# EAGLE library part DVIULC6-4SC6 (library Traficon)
Ultra low capacitance ESD protection
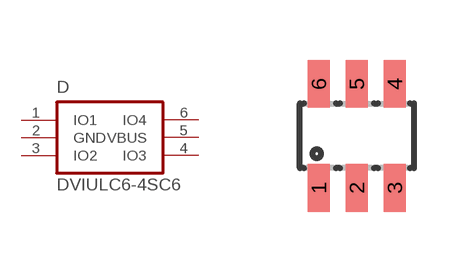
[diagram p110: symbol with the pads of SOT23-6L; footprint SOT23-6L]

Designator prefix D

## DVIULC6-4SC6  [SOT23-6L]
1  IO1
2  GND
3  IO2
4  IO3
5  VBUS
6  IO4

## Footprint SOT23-6L (pad centres in mm)
Small Outline Transistor
smd 0.55 x 1.2: 1 -0.95,-1.3; 2 0,-1.3; 3 0.95,-1.3; 4 0.95,1.3; 5 0,1.3; 6 -0.95,1.3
